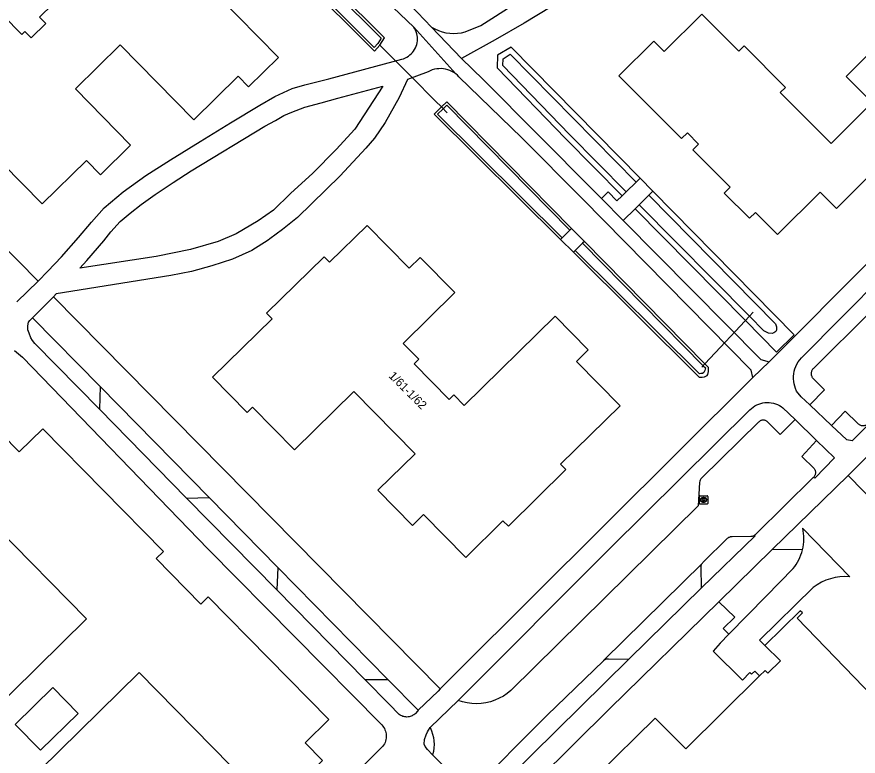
# Model space of a CAD drawing. Extents: x 162791 to 163827, y 385795 to 386523.
# Drawn here: x 162989.1 to 163089.2, y 386026.9 to 386115 of the extents above; entities that cross this region are included whole.
import ezdxf

# ---------------------------------------------------------------- set-up
doc = ezdxf.new("R2010")
doc.units = 0
for name, color, linetype in [('IMGEO_Duiker', 7, 'Continuous'), ('IMGEO_Erf', 7, 'Continuous'), ('IMGEO_Kolk', 7, 'Continuous'), ('IMGEO_Pand', 7, 'Continuous'), ('IMGEO_Pand_nummerreeks', 7, 'Continuous'), ('IMGEO_Parkeervlak_open', 7, 'Continuous'), ('IMGEO_Rijbaan_lokaal_gesloten', 7, 'Continuous'), ('IMGEO_Voetpad_gesloten', 7, 'Continuous'), ('IMGEO_Voetpad_open', 7, 'Continuous'), ('IMGEO_Waterloop', 7, 'Continuous'), ('IMGEO_Woonerf_gesloten', 7, 'Continuous'), ('IMGEO_Woonerf_open', 7, 'Continuous')]:
    doc.layers.add(name, color=color, linetype=linetype)

msp = doc.modelspace()

# ---------------------------------------------------------------- linework, layer by layer
at = {"layer": 'IMGEO_Duiker'}
for points in [[(163040.32, 386103.54), (163039.62, 386104.24), (163038.93, 386104.94), (163036.1, 386107.79), (163032.29, 386111.61)], [(163070.62, 386073.26), (163070.99, 386073.65), (163073.45, 386076.29), (163074.62, 386077.55), (163076.28, 386079.33), (163076.73, 386079.81)]]:
    msp.add_lwpolyline(points, dxfattribs=at)
at = {"layer": 'IMGEO_Erf'}
for points in [[(162998.9, 386143.57), (163000, 386142.43), (163006.8, 386135.45), (163013.12, 386129.5), (163014.41, 386128.09), (163031.64, 386110.89), (163032.29, 386111.61), (163032.84, 386112.46), (163015.79, 386129.44), (163014.42, 386130.87), (163000.25, 386145.04)], [(163063.28, 386095.75), (163047.93, 386111.38), (163046.3, 386110.39), (163046.24, 386108.91), (163054.39, 386100.49), (163061.14, 386093.66)], [(163055.12, 386089.77), (163040.27, 386104.86), (163039.62, 386104.24), (163038.75, 386103.4), (163053.79, 386088.47)], [(163062.67, 386092.12), (163075.81, 386078.83), (163079.51, 386075.04), (163081.6, 386077.12), (163064.79, 386094.23)], [(163055.33, 386086.94), (163070.32, 386072.07), (163070.64, 386072.07), (163070.93, 386072.09), (163071.24, 386072.26), (163071.32, 386072.39), (163071.41, 386072.76), (163071.42, 386073.21), (163070.99, 386073.65), (163056.64, 386088.23)]]:
    msp.add_lwpolyline(points, dxfattribs=at)
at = {"layer": 'IMGEO_Kolk'}
for p, q in [((163070.33, 386057.02), (163070.33, 386057.88)), ((163070.4, 386057.95), (163071.25, 386057.95)), ((163070.82, 386057.73), (163070.84, 386057.73)), ((163071.33, 386057.88), (163071.33, 386057.02)), ((163071.25, 386056.95), (163070.4, 386056.95)), ((163070.84, 386057.17), (163070.81, 386057.17))]:
    msp.add_line(p, q, dxfattribs=at)
for points in [[(163070.33, 386057.02), (163070.33, 386057.88)], [(163070.4, 386057.95), (163071.25, 386057.95)], [(163071.33, 386057.88), (163071.33, 386057.02)], [(163071.25, 386056.95), (163070.4, 386056.95)], [(163070.65, 386057.65), (163070.77, 386057.65), (163070.77, 386057.5), (163070.9, 386057.65), (163071.07, 386057.65), (163070.92, 386057.5), (163071.07, 386057.25), (163070.92, 386057.25), (163070.84, 386057.41), (163070.77, 386057.35), (163070.77, 386057.25), (163070.65, 386057.25), (163070.65, 386057.65)]]:
    msp.add_lwpolyline(points, dxfattribs=at)
for centre, start, end in [((163070.4, 386057.87), 91.552, 178.448), ((163070.4, 386057.87), 91.552, 178.448), ((163071.25, 386057.87), 1.552, 88.448), ((163071.25, 386057.87), 1.552, 88.448), ((163070.4, 386057.03), 181.552, 268.448), ((163070.4, 386057.03), 181.552, 268.448), ((163071.25, 386057.03), 271.552, 358.448), ((163071.25, 386057.03), 271.552, 358.448)]:
    msp.add_arc(centre, 0.0765, start, end, dxfattribs=at)
for centre, major_axis, ratio, start_param, end_param in [((163070.81, 386057.45), (-0.387, 0.002), 0.722429, 4.712389, 7.853982), ((163070.84, 386057.45), (-0.39, 0.002), 0.717154, 1.570796, 4.712389)]:
    msp.add_ellipse(centre, major_axis=major_axis, ratio=ratio, start_param=start_param, end_param=end_param, dxfattribs=at)
at = {"layer": 'IMGEO_Pand'}
for points in [[(162980.76, 386121.94), (162989.67, 386112.87), (162990.05, 386113.24), (162990.8, 386112.47), (162992.54, 386114.18), (162991.78, 386114.95), (162995.01, 386118.12)], [(163010.57, 386120), (163020.25, 386110.15)], [(163020.25, 386110.15), (163016.67, 386106.63), (163015.42, 386107.91), (163010.14, 386102.72), (163001.39, 386111.62), (162996.06, 386106.38), (163002.63, 386099.69), (162999.05, 386096.17), (162997.38, 386097.87), (162992.1, 386092.69), (162985.01, 386099.9), (162983.41, 386098.34), (162978.74, 386103.09), (162980.33, 386104.65), (162970.65, 386114.51), (162974.23, 386118.03)], [(163096.43, 386101.92), (163086.65, 386092.15), (163084.69, 386094.11), (163079.63, 386089.05), (163076.99, 386091.69), (163076.29, 386090.99), (163073.29, 386093.99), (163073.99, 386094.69), (163069.54, 386099.14), (163070.23, 386099.83), (163068.9, 386101.16), (163068.21, 386100.47), (163060.74, 386107.94), (163064.89, 386112.09), (163066.15, 386110.83), (163070.61, 386115.28), (163075.01, 386110.88), (163075.64, 386111.5), (163080.57, 386106.57), (163079.95, 386105.95), (163086.01, 386099.88), (163090.89, 386104.76), (163087.79, 386107.86), (163094.81, 386114.88)], [(163041.21, 386082.13), (163035.06, 386076.09), (163036.92, 386074.2), (163036.38, 386073.67), (163040.55, 386069.42), (163041.09, 386069.95), (163042.33, 386068.69), (163053.16, 386079.33), (163057.09, 386075.33), (163055.69, 386073.95), (163060.89, 386068.67), (163053.81, 386061.71), (163054.45, 386061.06), (163047.59, 386054.32), (163046.95, 386054.97), (163042.51, 386050.6), (163037.49, 386055.7), (163036.18, 386054.41), (163032.07, 386058.6), (163036.49, 386062.94), (163029.21, 386070.35), (163022.15, 386063.41), (163017.14, 386068.51), (163016.5, 386067.87), (163012.38, 386072.06), (163019.46, 386079.02), (163018.82, 386079.67), (163025.68, 386086.41), (163026.32, 386085.76), (163030.77, 386090.13), (163035.78, 386085.03), (163037.09, 386086.32), (163041.21, 386082.13)], [(162999.83, 386005.36), (163001.89, 386003.26), (163012.48, 386013.66), (163007.39, 386018.84), (163002.69, 386014.21), (162991.83, 386025.26), (163003.66, 386036.89), (163014.52, 386025.84), (163009.81, 386021.21), (163014.89, 386016.04), (163025.48, 386026.44), (163023.41, 386028.54), (163026.22, 386031.3), (163011.87, 386045.9), (163011, 386045.05), (163005.67, 386050.48), (163006.53, 386051.33), (162992.18, 386065.93), (162989.38, 386063.17), (162987.31, 386065.27)], [(162986.52, 386054.33), (162997.38, 386043.28), (162985.55, 386031.65)], [(163100.05, 386024.64), (163081.98, 386043.39), (163082.6, 386044), (163082.34, 386044.26), (163078.12, 386040.12)], [(163078.12, 386040.12), (163079.97, 386038.29), (163078.47, 386036.83), (163078.15, 386037.15), (163077.49, 386036.5)], [(163077.49, 386036.5), (163068.7, 386027.82), (163065.05, 386031.48), (163058.14, 386024.66), (163061.75, 386021), (163041.79, 386001.29)], [(162991.9, 386027.64), (162988.88, 386030.71), (162993.37, 386035.12), (162996.39, 386032.04), (162991.9, 386027.64)]]:
    msp.add_lwpolyline(points, dxfattribs=at)
at = {"layer": 'IMGEO_Parkeervlak_open'}
for points in [[(162999, 386070.95), (162998.91, 386068.26)], [(163011.98, 386057.73), (162999, 386070.95)], [(163009.29, 386057.68), (162998.91, 386068.26)], [(163009.29, 386057.68), (163011.98, 386057.73)], [(163058.97, 386038.36), (163070.68, 386049.94)], [(163070.56, 386046.97), (163070.53, 386049.44), (163070.52, 386049.5), (163070.53, 386049.56), (163070.53, 386049.62), (163070.55, 386049.68), (163070.56, 386049.73), (163070.59, 386049.79), (163070.61, 386049.84), (163070.65, 386049.89), (163070.68, 386049.94)], [(163020.16, 386049.41), (163020.03, 386046.73)], [(163033.25, 386036.07), (163020.16, 386049.41)], [(163030.49, 386036.07), (163020.03, 386046.73)], [(163070.56, 386046.97), (163061.92, 386038.49)], [(163058.97, 386038.36), (163059.02, 386038.4), (163059.07, 386038.43), (163059.13, 386038.47), (163059.19, 386038.49), (163059.25, 386038.52), (163059.31, 386038.53), (163059.38, 386038.54), (163059.44, 386038.55), (163059.51, 386038.55), (163061.92, 386038.49)], [(163030.49, 386036.07), (163033.25, 386036.07)]]:
    msp.add_lwpolyline(points, dxfattribs=at)
at = {"layer": 'IMGEO_Rijbaan_lokaal_gesloten'}
for points in [[(163090.23, 386062.55), (163088.02, 386060.38)], [(163088.02, 386060.38), (163122.64, 386025)]]:
    msp.add_lwpolyline(points, dxfattribs=at)
at = {"layer": 'IMGEO_Voetpad_gesloten'}
for points in [[(163088.23, 386048.29), (163082.62, 386054.1)], [(163073.83, 386041.47), (163078.26, 386045.98), (163081.49, 386049.28)], [(163078.12, 386040.12), (163077.5, 386040.77), (163083.88, 386047.01)], [(163073.83, 386041.47), (163072.8, 386040.38), (163071.97, 386039.44), (163075.47, 386036), (163076.34, 386036.89), (163076.55, 386036.71), (163076.94, 386037.06), (163077.49, 386036.5)]]:
    msp.add_lwpolyline(points, dxfattribs=at)
for centre, radius, start, end in [((163077.08, 386052.86), 5.68, 346.0989, 12.6264), ((163077.08, 386052.86), 5.68, 320.8698, 346.1035), ((163087.68, 386042.11), 6.21, 84.964, 127.8122)]:
    msp.add_arc(centre, radius, start, end, dxfattribs=at)
at = {"layer": 'IMGEO_Voetpad_open'}
for points in [[(163061.63, 386094.14), (163062.8, 386095.28)], [(163062.8, 386095.28), (163063.28, 386095.75)], [(163063.28, 386095.75), (163064.79, 386094.23)], [(163058.66, 386093.35), (163059.46, 386094.15), (163060.52, 386093.06), (163061.14, 386093.66)], [(163061.14, 386093.66), (163061.63, 386094.14)], [(163064.79, 386094.23), (163064.3, 386093.74)], [(163058.66, 386093.35), (163061.26, 386090.73)], [(163064.3, 386093.74), (163063.15, 386092.6)], [(163062.67, 386092.12), (163061.26, 386090.73)], [(163063.15, 386092.6), (163062.67, 386092.12)], [(163055.12, 386089.77), (163054.91, 386089.56)], [(163056.64, 386088.23), (163055.12, 386089.77)], [(163054.91, 386089.56), (163054.01, 386088.67)], [(163054.01, 386088.67), (163053.79, 386088.47)], [(163053.79, 386088.47), (163055.33, 386086.94)], [(163055.54, 386087.15), (163056.43, 386088.02)], [(163056.64, 386088.23), (163056.43, 386088.02)], [(163055.54, 386087.15), (163055.33, 386086.94)], [(163072.63, 386045.31), (163078.99, 386051.54)], [(163082.59, 386051.5), (163078.99, 386051.54)], [(163072.63, 386045.31), (163074.56, 386043.51), (163073.15, 386042.16), (163073.83, 386041.47)]]:
    msp.add_lwpolyline(points, dxfattribs=at)
at = {"layer": 'IMGEO_Waterloop'}
for points in [[(163000.06, 386144.81), (163014.01, 386130.86), (163014.21, 386130.65), (163015.58, 386129.23), (163015.78, 386129.02), (163032.46, 386112.42), (163032.05, 386111.79), (163031.63, 386111.32), (163014.83, 386128.09)], [(163061.63, 386094.14), (163054.87, 386100.97), (163046.94, 386109.17), (163046.97, 386109.99), (163047.82, 386110.51), (163062.8, 386095.28)], [(163054.91, 386089.56), (163040.26, 386104.44), (163039.83, 386104.03), (163039.17, 386103.39), (163054.01, 386088.67)], [(163064.3, 386093.74), (163079.37, 386078.41), (163079.51, 386078.08), (163079.52, 386077.65), (163079.44, 386077.52), (163079.18, 386077.33), (163079, 386077.27), (163078.56, 386077.3), (163077.98, 386077.59), (163076.28, 386079.33), (163063.15, 386092.6)], [(163056.43, 386088.02), (163070.79, 386073.43), (163071.04, 386073.17), (163070.96, 386072.86), (163070.91, 386072.7), (163070.86, 386072.63), (163070.68, 386072.52), (163070.52, 386072.49), (163070.33, 386072.48), (163055.54, 386087.15)]]:
    msp.add_lwpolyline(points, dxfattribs=at)
at = {"layer": 'IMGEO_Woonerf_gesloten'}
for points in [[(163078.62, 386073.9), (163090.95, 386086.25), (163109.57, 386104.88), (163137.82, 386133.23), (163155.34, 386150.64)], [(163083.47, 386068.77), (163082.46, 386069.73), (163081.9, 386070.42), (163081.78, 386070.7), (163081.68, 386070.98), (163081.6, 386071.27), (163081.55, 386071.57), (163081.53, 386071.87), (163081.53, 386072.18), (163081.56, 386072.48), (163081.62, 386072.78), (163081.7, 386073.07), (163081.81, 386073.35), (163081.94, 386073.62), (163082.1, 386073.88), (163082.27, 386074.13), (163082.47, 386074.36), (163097.04, 386089.07), (163117.96, 386109.83), (163142.94, 386134.85), (163156.62, 386148.64)], [(163038.43, 386113.76), (163038.84, 386113.54), (163039.27, 386113.34), (163039.71, 386113.19), (163040.16, 386113.08), (163040.62, 386113.02), (163041.09, 386112.99), (163041.55, 386113.01), (163042.01, 386113.07), (163042.47, 386113.17), (163044.33, 386113.93), (163048.38, 386116.51), (163055.95, 386121.44), (163058.68, 386123.89), (163060.17, 386125.34), (163064.9, 386130.13), (163071.55, 386137.29)], [(163073.09, 386135.24), (163062.74, 386124.27), (163061.15, 386122.84), (163057.04, 386119.12), (163054.85, 386117.59), (163052.69, 386116.17), (163049.48, 386114.23), (163046.01, 386112.24), (163042.01, 386110.03)], [(162991.63, 386083.51), (162992.76, 386084.69), (162994.4, 386086.39), (162996.43, 386088.68), (162997.98, 386090.52), (162999.5, 386092.25), (163001.75, 386094.13), (163004.45, 386096.1), (163007.36, 386097.95), (163010.91, 386100.14), (163014.53, 386102.37), (163018.01, 386104.47), (163019.81, 386105.48), (163021.84, 386106.43), (163023.35, 386106.88), (163026.24, 386107.61), (163034.93, 386109.93), (163035.13, 386109.99), (163035.33, 386110.08), (163035.52, 386110.18), (163035.71, 386110.29), (163035.88, 386110.43), (163036.04, 386110.57), (163036.18, 386110.73), (163036.31, 386110.9), (163036.43, 386111.09), (163036.53, 386111.28), (163036.61, 386111.48), (163036.68, 386111.68), (163036.73, 386111.89), (163036.76, 386112.1), (163036.77, 386112.32), (163036.76, 386112.54), (163036.73, 386112.75), (163036.69, 386112.96), (163036.62, 386113.17), (163036.54, 386113.37), (163036.45, 386113.56), (163036.33, 386113.74)], [(163041.32, 386108.18), (163036.33, 386113.74)], [(163038.43, 386113.76), (163042.01, 386110.03)], [(163041.32, 386108.18), (163041.1, 386108.34), (163040.87, 386108.47), (163040.63, 386108.58), (163040.38, 386108.67), (163040.12, 386108.74), (163039.86, 386108.79), (163039.59, 386108.81), (163039.33, 386108.8), (163039.06, 386108.78), (163038.8, 386108.73), (163038.54, 386108.66), (163038.3, 386108.56), (163038.05, 386108.44), (163035.57, 386107.51), (163034.59, 386105.37), (163032.93, 386102.39), (163031.64, 386100.54), (163030.64, 386099.34), (163027.57, 386096.04), (163022.48, 386091.08), (163020.69, 386089.64), (163019.2, 386088.54), (163019.01, 386088.4), (163017.06, 386087.16), (163014.76, 386086.1), (163012.3, 386085.31), (163009.88, 386084.65), (163007.4, 386084.18), (162993.77, 386081.99), (162993.46, 386081.65)], [(163030.28, 386106.1), (163032.64, 386106.71), (163029.31, 386101.6), (163027.09, 386099.16), (163024.33, 386096.37), (163021.67, 386093.94), (163019.64, 386091.97), (163017.82, 386090.69), (163015.2, 386089.13), (163013.06, 386088.21), (163009.76, 386087.28), (163005.68, 386086.42), (162996.59, 386085.05), (162997.43, 386085.96), (162999.43, 386088.32), (163000.26, 386089.36), (163001.4, 386090.59), (163002.56, 386091.58), (163003.9, 386092.61), (163005.57, 386093.82), (163007.71, 386095.24), (163009.85, 386096.62), (163018.62, 386101.96), (163019.88, 386102.62), (163020.87, 386103.24), (163021.81, 386103.64), (163023.36, 386104.23), (163025.32, 386104.75), (163027.3, 386105.3), (163030.28, 386106.1)], [(162991.63, 386083.51), (162989.08, 386081.02)], [(162990.94, 386079.15), (162993.46, 386081.65)], [(162998.91, 386068.26), (162991.25, 386076.07), (162990.96, 386076.42), (162990.77, 386076.75), (162990.55, 386077.29), (162990.4, 386077.71), (162990.39, 386078.03), (162990.4, 386078.18), (162990.48, 386078.61), (162990.62, 386078.83), (162990.94, 386079.15)], [(162988.81, 386075.23), (162989.77, 386074.46), (163011.85, 386051.6), (163032.4, 386030.78), (163032.53, 386030.66), (163032.64, 386030.53), (163032.74, 386030.39), (163032.83, 386030.24), (163032.9, 386030.09), (163032.96, 386029.92), (163033.01, 386029.76), (163033.04, 386029.59), (163033.06, 386029.42), (163033.06, 386029.25), (163033.04, 386029.08), (163033.01, 386028.91), (163032.97, 386028.74), (163032.91, 386028.58), (163032.84, 386028.42), (163032.75, 386028.27), (163032.65, 386028.13), (163032.54, 386028), (163032.42, 386027.88), (163032.29, 386027.77), (162996.59, 385991.77)], [(163078.62, 386073.9), (163076.7, 386072.03)], [(163039.48, 386034.95), (163041.52, 386037.03), (163076.7, 386072.03)], [(163041.61, 386033.57), (163059.72, 386051.71), (163076.33, 386068.17), (163076.52, 386068.35), (163076.72, 386068.5), (163076.93, 386068.64), (163077.15, 386068.76), (163077.39, 386068.86), (163077.63, 386068.94), (163077.88, 386069), (163078.13, 386069.04), (163078.38, 386069.05), (163078.64, 386069.05), (163078.89, 386069.02), (163079.14, 386068.97), (163079.39, 386068.9), (163079.62, 386068.8), (163079.85, 386068.69), (163080.07, 386068.56), (163080.27, 386068.41), (163081.71, 386067.01)], [(163086.07, 386066.31), (163083.47, 386068.77)], [(163081.71, 386067.01), (163084.27, 386064.54)], [(163090.46, 386066.59), (163090.54, 386066.5), (163088.52, 386064.5), (163087.86, 386064.6), (163086.07, 386066.31)], [(163084.27, 386064.54), (163086.4, 386062.46), (163084.05, 386060.03), (163083.9, 386060.12)], [(163083.9, 386060.12), (163083.85, 386060.07), (163077.08, 386053.41), (163077.04, 386053.36), (163076.99, 386053.32), (163076.95, 386053.28), (163076.89, 386053.24)], [(163078.99, 386051.54), (163088.02, 386060.38)], [(163020.03, 386046.73), (163009.29, 386057.68)], [(163076.89, 386053.24), (163076.96, 386053.17), (163070.56, 386046.97)], [(163033.75, 386006.93), (163059.67, 386032.61), (163072.63, 386045.31)], [(163061.92, 386038.49), (163044.67, 386021.48), (163042.97, 386022.55)], [(163036.86, 386032.4), (163036.76, 386032.31), (163036.53, 386032.04), (163036.44, 386031.95), (163036.34, 386031.88), (163036.24, 386031.81), (163036.13, 386031.75), (163036.01, 386031.7), (163035.89, 386031.66), (163035.77, 386031.63), (163035.65, 386031.61), (163035.52, 386031.6), (163035.4, 386031.61), (163035.28, 386031.62), (163035.15, 386031.65), (163035.03, 386031.68), (163034.92, 386031.73), (163034.81, 386031.78), (163034.7, 386031.84), (163034.6, 386031.92), (163033.39, 386033.12), (163030.49, 386036.07)], [(163039.48, 386034.95), (163039.23, 386034.7), (163036.86, 386032.4)], [(163038.28, 386030.35), (163041.61, 386033.57)], [(163038.58, 386027.1), (163037.98, 386027.72), (163037.68, 386028.1), (163037.58, 386028.38), (163037.6, 386028.93), (163037.81, 386029.48), (163037.96, 386029.84), (163038.1, 386030.05), (163038.28, 386030.35)], [(163042.97, 386022.55), (163039.34, 386026.32), (163038.58, 386027.1)]]:
    msp.add_lwpolyline(points, dxfattribs=at)
at = {"layer": 'IMGEO_Woonerf_open'}
for points in [[(163036.33, 386113.74), (163031.42, 386118.47), (163009.12, 386141.02), (163006.09, 386144.1), (163004.76, 386145.27)], [(163009.45, 386143.12), (163009.59, 386142.98), (163009.74, 386142.84), (163011.85, 386140.66), (163036.77, 386115.49), (163038.43, 386113.76)], [(162958.39, 386117.42), (162965.64, 386109.89), (162991.63, 386083.51)], [(163042.01, 386110.03), (163044.61, 386107.5), (163057.74, 386094.28), (163058.66, 386093.35)], [(163076.7, 386072.03), (163076.48, 386072.91), (163056.43, 386093.32), (163049.21, 386100.56), (163041.71, 386107.83), (163041.52, 386108.01), (163041.32, 386108.18)], [(163061.26, 386090.73), (163077.65, 386074.19), (163078.62, 386073.9)], [(162993.46, 386081.65), (163039.48, 386034.95)], [(163083.47, 386068.77), (163085.2, 386070.55), (163083.91, 386071.86), (163083.86, 386071.92), (163083.81, 386071.99), (163083.77, 386072.06), (163083.74, 386072.13), (163083.71, 386072.21), (163083.69, 386072.28), (163083.67, 386072.36), (163083.67, 386072.44), (163083.66, 386072.52), (163083.67, 386072.6), (163083.68, 386072.68), (163083.71, 386072.76), (163083.73, 386072.84), (163083.77, 386072.91), (163083.81, 386072.98), (163083.85, 386073.05), (163083.9, 386073.11), (163090.68, 386079.84)], [(162990.94, 386079.15), (162999, 386070.95)], [(163086.07, 386066.31), (163087.69, 386068.03), (163089.17, 386066.55), (163089.23, 386066.5), (163089.29, 386066.46), (163089.36, 386066.42), (163089.43, 386066.38), (163089.51, 386066.35), (163089.58, 386066.33), (163089.66, 386066.32), (163089.74, 386066.31), (163089.82, 386066.31), (163089.9, 386066.32), (163089.98, 386066.33), (163090.05, 386066.35), (163090.13, 386066.37), (163090.2, 386066.41), (163090.27, 386066.44), (163090.33, 386066.49), (163090.4, 386066.54), (163090.46, 386066.59)], [(163081.71, 386067.01), (163079.96, 386065.23), (163078.52, 386066.66), (163078.48, 386066.71), (163078.43, 386066.76), (163078.38, 386066.8), (163078.33, 386066.84), (163078.27, 386066.87), (163078.21, 386066.9), (163078.15, 386066.92), (163078.09, 386066.93), (163078.02, 386066.95), (163077.96, 386066.95), (163077.89, 386066.95), (163077.83, 386066.94), (163077.77, 386066.93), (163077.7, 386066.91), (163077.64, 386066.89), (163077.58, 386066.86), (163077.53, 386066.83), (163077.48, 386066.79), (163077.43, 386066.74), (163077.38, 386066.7), (163070.61, 386060.1), (163070.52, 386059.96), (163070.44, 386059.82), (163070.38, 386059.67), (163070.33, 386059.51), (163070.2, 386056.76), (163047.9, 386034.76), (163047.46, 386034.41), (163047, 386034.1), (163046.51, 386033.83), (163046, 386033.6), (163045.46, 386033.42), (163044.92, 386033.3), (163044.37, 386033.22), (163043.81, 386033.19), (163043.25, 386033.21), (163042.69, 386033.28), (163042.15, 386033.4), (163041.61, 386033.57)], [(163084.27, 386064.54), (163082.54, 386062.64), (163083.99, 386061.19), (163084.03, 386061.12), (163084.07, 386061.05), (163084.09, 386060.98), (163084.11, 386060.91), (163084.13, 386060.83), (163084.14, 386060.75), (163084.14, 386060.68), (163084.13, 386060.6), (163084.12, 386060.52), (163084.1, 386060.45), (163084.07, 386060.38), (163084.04, 386060.31), (163084, 386060.24), (163083.95, 386060.18), (163083.9, 386060.12)], [(163011.98, 386057.73), (163020.16, 386049.41)], [(163070.68, 386049.94), (163070.73, 386049.99), (163070.77, 386050.03), (163073.69, 386052.88), (163073.74, 386052.93), (163073.8, 386052.97), (163073.85, 386053), (163073.91, 386053.03), (163073.98, 386053.06), (163074.04, 386053.08), (163074.11, 386053.09), (163074.18, 386053.1), (163074.24, 386053.1), (163076.46, 386053.13), (163076.52, 386053.13), (163076.59, 386053.14), (163076.65, 386053.15), (163076.72, 386053.16), (163076.78, 386053.18), (163076.84, 386053.21), (163076.89, 386053.24)], [(163042.97, 386022.55), (163052.2, 386031.81), (163058.92, 386038.31), (163058.97, 386038.36)], [(163033.25, 386036.07), (163036.86, 386032.4)], [(163038.28, 386030.35), (163038.44, 386029.97), (163038.58, 386029.57), (163038.67, 386029.17), (163038.73, 386028.75), (163038.75, 386028.34), (163038.73, 386027.92), (163038.67, 386027.51), (163038.58, 386027.1)]]:
    msp.add_lwpolyline(points, dxfattribs=at)

# ---------------------------------------------------------------- texts
at = {"layer": 'IMGEO_Pand_nummerreeks'}
msp.add_text('1/61-1/62', height=1, rotation=314.9896, dxfattribs=at).set_placement((163033.28, 386072.15))

doc.saveas('drawing.dxf')
